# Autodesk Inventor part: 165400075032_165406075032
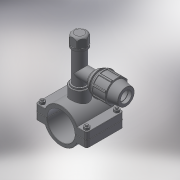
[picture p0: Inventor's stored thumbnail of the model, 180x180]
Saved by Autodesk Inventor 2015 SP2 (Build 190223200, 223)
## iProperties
Created: 2017-05
Part Number: 165400075032_165406075032
Material: Generic
Description: PLASSON TAPPER FOR PE+PVC PIPE 75-32
Document SubType Name: Modeling
Designer: KIM
Density: 1 g/cm^3
Appearance: Default
Author: KIM
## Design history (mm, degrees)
derived "16540.ipt"
feature "Solid1::16540.ipt"
feature "Solid2::16540.ipt"
tag "TaggingFeature1"
body "Solid1"
other parameters: "d0" = 93.75, "d1" = 122, "d2" = 37.5, "d3" = 75, "d4" = 98, "d5" = 0, "d6" = 6.1, "d7" = 122, "d8" = 0.1, "d10" = 0, "d11" = 0.75, "d14" = 50.6376, "d20" = 0.75, "d23" = 0.75, "d37" = 8, "d38" = 45.5, "d39" = 0, "d40" = 3, "d41" = 5, "d42" = 0, "d43" = 6, "d44" = 3, "d45" = 0, "d46" = 0.75, "d51" = 72, "d52" = 38.952, "d53" = 25, "d54" = 0, "d55" = 32, "d57" = 0, "d58" = 81, "d60" = 0, "d63" = 8, "d66" = 82, "d67" = 32, "d68" = 9.08333, "d69" = 21.8, "d70" = 64, "d71" = 48, "d72" = 1.55714, "d73" = 51.2, "d74" = 120 deg, "d75" = 48, "d76" = 10 deg, "d77" = 57.6, "d78" = 32.7, "d79" = 71, "d80" = 25.6, "d81" = 109, "d82" = 7.1, "d87" = 15.57143, "d90" = 59.52, "d91" = 35 deg, "d92" = 17.5 deg, "d94" = 0, "d96" = 360 deg, "d98" = 0.64, "d99" = 78.1, "d100" = 35.0568, "d101" = 135 deg, "d102" = 1.28, "d105" = 3.2, "d106" = 0, "d107" = 0.1, "d108" = 35.0568, "d109" = 42.8472, "d111" = 26, "d112" = 6.5, "d113" = 3.63333, "d116" = 0, "d117" = 38, "d118" = 21.8, "d119" = 0, "d122" = 57, "d_" = 75, "B_" = 32, "G_" = 38.952, "A_" = 72, "L_" = 122, "L_1" = 98, "l_2" = 25, "d_1" = 32, "E_" = 64, "l_" = 71, "H_" = 109, "H_1" = 57
